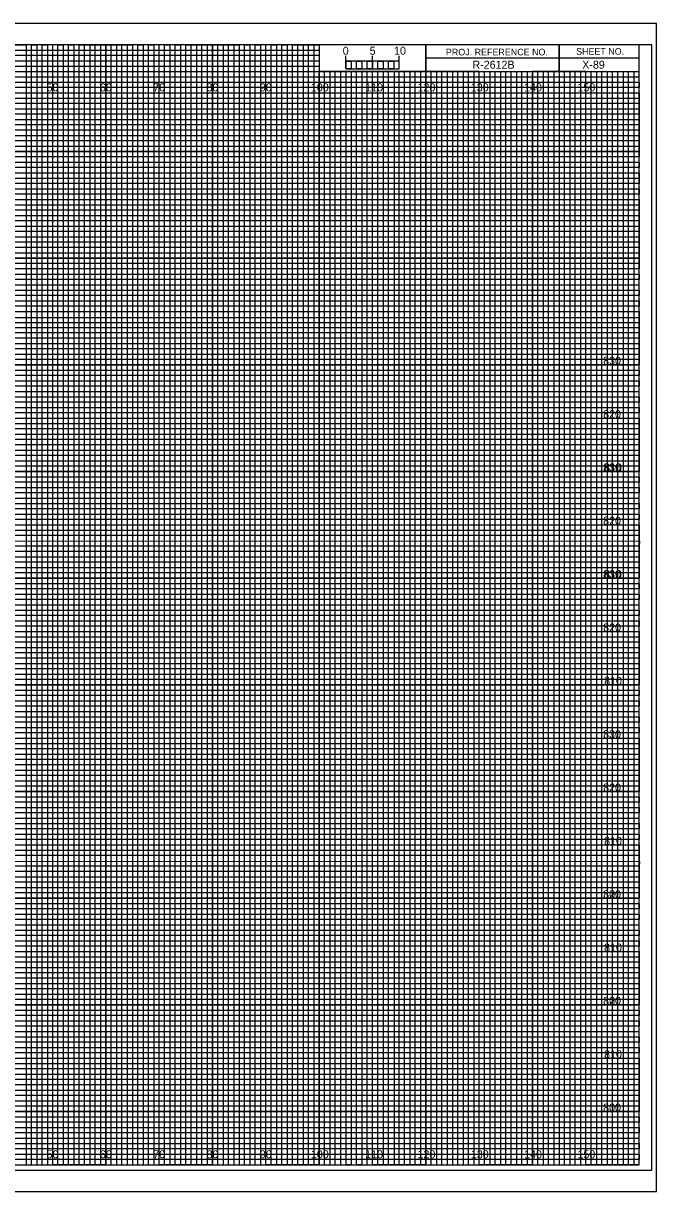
# Model space of a CAD drawing. Extents: x -13 to 323, y -5 to 214.
# Drawn here: x 204.5 to 323.3, y -5 to 214 of the extents above; entities that cross this region are included whole.
import ezdxf

# ---------------------------------------------------------------- set-up
doc = ezdxf.new("R2010")
doc.units = 0
for name, color, linetype in [('Prop XS Bar Scale Labels', 7, 'Continuous'), ('Prop XS Elevation Labels', 7, 'Continuous'), ('Prop XS Offset Labels', 7, 'Continuous'), ('Prop XS Project Number', 7, 'Continuous'), ('Prop XS Sheet Number', 7, 'Continuous'), ('Sheet Cross Section CELL', 7, 'Continuous'), ('Sheet Cross Section Grid Major CELL', 7, 'Continuous'), ('Sheet Cross Section Grid Middle CELL', 7, 'Continuous'), ('Sheet Cross Section Grid Minor 1 CELL', 7, 'Continuous'), ('Sheet Cross Section Grid Minor 2 CELL', 7, 'Continuous'), ('Sheet Cross Section Scale CELL', 7, 'Continuous'), ('Sheet Cutting Line CELL', 7, 'Continuous'), ('Sheet DOT Grid CELL', 7, 'Continuous'), ('Sheet Plot Border Inside CELL', 7, 'Continuous'), ('Sheet Plot Border Outside CELL', 7, 'Continuous')]:
    doc.layers.add(name, color=color, linetype=linetype)

msp = doc.modelspace()

# ---------------------------------------------------------------- linework, layer by layer
at = {"layer": 'Sheet Cross Section CELL'}
for p, q in [((305, 210), (305, 205)), ((305, 205), (305, 210)), ((280, 207.5), (280, 205)), ((320, 207.49), (280, 207.49)), ((280, 205), (320, 205))]:
    msp.add_line(p, q, dxfattribs=at)
for points in [[(320, 210), (0, 210), (0, 0), (320, 0)], [(280, 210), (260, 210), (260, 205.03), (280, 205.03)], [(320, 210), (280, 210), (280, 205), (320, 205)]]:
    msp.add_lwpolyline(points, close=True, dxfattribs=at)
at = {"layer": 'Sheet Cross Section Grid Major CELL'}
for p, q in [((210, 210), (200, 210)), ((210, 0), (210, 210)), ((230, 210), (220, 210)), ((220, 210), (220, 0)), ((230, 0), (230, 210)), ((250, 210), (240, 210)), ((240, 210), (240, 0)), ((250, 0), (250, 210)), ((260, 210), (260, 0)), ((270, 0), (270, 205)), ((290, 205), (280, 205)), ((280, 205), (280, 0)), ((290, 0), (290, 205)), ((310, 205), (300, 205)), ((300, 205), (300, 0)), ((310, 0), (310, 205)), ((220, 0), (210, 0)), ((240, 0), (230, 0)), ((260, 0), (250, 0)), ((280, 0), (270, 0)), ((300, 0), (290, 0)), ((320, 0), (310, 0)), ((320, 0), (320, 0))]:
    msp.add_line(p, q, dxfattribs=at)
for points in [[(0, 200), (320, 200), (320, 190), (0, 190)], [(0, 180), (320, 180), (320, 170), (0, 170)], [(0, 160), (320, 160), (320, 150), (0, 150)], [(0, 140), (320, 140), (320, 130), (0, 130)], [(0, 120), (320, 120), (320, 110), (0, 110)], [(0, 100), (320, 100), (320, 90), (0, 90)], [(0, 80), (320, 80), (320, 70), (0, 70)], [(0, 60), (320, 60), (320, 50), (0, 50)], [(0, 40), (320, 40), (320, 30), (0, 30)], [(0, 20), (320, 20), (320, 10), (0, 10)]]:
    msp.add_lwpolyline(points, dxfattribs=at)
at = {"layer": 'Sheet Cross Section Grid Middle CELL'}
for points in [[(195, 210), (205, 210), (205, 0), (215, 0), (215, 210), (225, 210), (225, 0), (235, 0), (235, 210), (245, 210), (245, 0), (255, 0), (255, 210), (259.93, 210), (260, 210), (260, 205), (264.99, 205), (264.99, 0), (275, 0), (275, 205), (285, 205), (285, 0), (295, 0), (295, 205), (305, 205), (305, 0), (315, 0), (315, 205)], [(0, 205), (275, 205)], [(0, 185), (320, 185), (320, 195), (0, 195)], [(0, 165), (320, 165), (320, 175), (0, 175)], [(0, 145), (320, 145), (320, 155), (0, 155)], [(0, 125), (320, 125), (320, 135), (0, 135)], [(0, 105), (320, 105), (320, 115), (0, 115)], [(0, 85), (320, 85), (320, 95), (0, 95)], [(0, 65), (320, 65), (320, 75), (0, 75)], [(0, 45), (320, 45), (320, 55), (0, 55)], [(0, 25), (320, 25), (320, 35), (0, 35)], [(0, 5), (320, 5), (320, 15), (0, 15)]]:
    msp.add_lwpolyline(points, dxfattribs=at)
at = {"layer": 'Sheet Cross Section Grid Minor 1 CELL'}
for p, q in [((0, 209), (260, 209)), ((260, 209), (260, 207.98)), ((260, 207.98), (0, 207.98)), ((0, 207), (260, 207)), ((260, 205.89), (0, 205.89)), ((260, 207), (260, 205.89)), ((0, 204), (320, 204))]:
    msp.add_line(p, q, dxfattribs=at)
for points in [[(0, 203), (270, 203), (320, 203), (320, 202), (0, 202)], [(0, 201), (320, 201), (320, 199), (0, 199)], [(0, 198), (320, 198), (320, 197), (0, 196.98)], [(0, 196), (320, 196), (320, 194), (0, 194)], [(0, 193), (320, 193), (320, 192), (0, 192)], [(0, 191), (320, 191), (320, 189), (0, 189)], [(0, 188), (320, 188), (320, 187), (0, 187)], [(0, 186), (320, 186), (320, 184), (0, 184)], [(0, 183), (320, 183), (320, 182), (0, 182)], [(0, 181), (320, 181), (320, 179), (0, 179)], [(0, 178), (320, 178), (320, 177), (0, 177)], [(0, 176), (320, 176), (320, 173.95), (320, 173), (320, 172), (0, 172)], [(0, 174), (320, 174), (320, 173), (0, 173)], [(0, 171), (320, 171), (320, 169), (0, 169.03)], [(0, 169.03), (320, 169), (320, 168), (0, 168)], [(0, 167), (320, 167), (320, 166), (0, 166)], [(0, 164), (320, 164), (320, 163), (0, 163)], [(0, 162), (320, 162), (320, 161), (0, 161)], [(-0.07, 158.89), (320, 158.89), (320, 157.88), (-0.07, 157.88)], [(0, 157), (320, 157), (320, 156), (0, 156)], [(0, 154), (320, 154), (320, 153), (0, 153)], [(0, 152), (320, 152), (320, 151), (0, 151)], [(0, 149), (320, 149), (320, 148), (0, 148)], [(0, 147), (320, 147), (320, 146), (0, 146)], [(0, 144), (320, 144), (320, 143), (0, 143)], [(0, 142), (320, 142), (320, 141), (0, 141)], [(0, 139), (320, 139), (319.99, 137.98), (0, 138)], [(0, 137), (320, 137), (320, 136), (0, 136)], [(0, 134), (320, 134), (320, 133), (0, 133)], [(0, 132), (320, 132), (320, 131), (0, 131)], [(0, 129), (320, 129), (320, 128), (0, 128)], [(0, 127), (320, 127), (320, 126), (0, 126)], [(0, 124), (320, 124), (320, 123), (0, 123)], [(0, 122), (320, 122), (320, 121), (0, 121)], [(0, 119), (320, 119), (320, 118), (0, 118)], [(0, 116.99), (320.07, 116.91), (320, 116), (0, 116)], [(0, 114), (320, 114), (320, 113), (0, 113)], [(0, 112), (320, 112), (320, 111), (0, 111)], [(0, 109), (320, 109), (320, 108), (0, 108)], [(0, 107), (320, 107), (320, 106), (0, 106)], [(0, 104), (320, 104), (320, 103), (0, 103)], [(0, 102), (320, 102), (320, 101), (0, 101)], [(0, 99), (320, 99), (320, 98), (0, 98)], [(0, 97), (320, 97), (320, 96), (0, 96)], [(0, 94), (320, 94), (320, 93), (0, 93)], [(0, 92), (320, 92), (320, 91), (0, 91)], [(0, 89), (320, 89), (320, 88), (0, 88)], [(0, 87), (320, 87), (320, 86), (0, 86)], [(0, 84), (320, 84), (320, 83), (0, 83)], [(0, 82), (320, 82), (320, 81), (0, 81)], [(0, 79), (320, 79), (319.99, 77.98), (0, 78)], [(0, 77), (320, 77), (320, 76), (0, 76)], [(0, 74), (320, 74), (320, 73), (0, 73)], [(0, 72), (320, 72), (320, 71), (0, 71)], [(0, 69), (320, 69), (320, 68), (0, 68)], [(0, 67), (320, 67), (320, 66), (0, 66)], [(0, 64), (320, 64), (320, 63), (0, 63)], [(0, 62), (320, 62), (320, 61), (0, 61)], [(0, 59), (320, 59), (320, 58), (0, 58)], [(0, 56.99), (320.07, 56.91), (320, 56), (0, 56)], [(0, 54), (320, 54), (320, 53), (0, 53)], [(0, 52), (320, 52), (320, 51), (0, 51)], [(0, 49), (320, 49), (320, 48), (0, 48)], [(0, 47), (320, 47), (320, 46), (0, 46)], [(0, 44), (320, 44), (320, 43), (0, 43)], [(0, 42), (320, 42), (320, 41), (0, 41)], [(0, 39), (320, 39), (320, 38), (0, 38)], [(0, 37), (320, 37), (320, 36), (0, 36)], [(0, 34), (320, 34), (320, 33), (0, 33)], [(0, 32), (320, 32), (320, 31), (0, 31)], [(0, 29), (320, 29), (320, 28), (0, 28)], [(0, 27), (320, 27), (320, 26), (0, 26)], [(0, 24), (320, 24), (320, 23), (0, 23)], [(0, 22), (320, 22), (320, 21), (0, 21)], [(0, 19), (320, 19), (320, 18), (0, 18)], [(0, 17), (320, 17), (320, 16), (0, 16)], [(0, 14), (320, 14), (320, 13), (0, 13)], [(0, 12), (320, 12), (320, 11), (0, 11)], [(0, 9), (320, 9), (320, 8), (0, 8)], [(0, 7), (320, 7), (320, 6), (0, 6)], [(0, 4), (320, 4), (320, 3), (0, 3)], [(0, 2), (320, 2), (320, 1), (0, 1)]]:
    msp.add_lwpolyline(points, dxfattribs=at)
at = {"layer": 'Sheet Cross Section Grid Minor 2 CELL'}
for p, q in [((267, 205), (266.01, 205)), ((266.01, 205), (266.01, 0)), ((267, 0), (267, 205)), ((269, 205), (268, 205)), ((268, 205), (268, 0)), ((269, 0), (269, 205)), ((266.01, 0), (265, 0)), ((268, 0), (267, 0))]:
    msp.add_line(p, q, dxfattribs=at)
for points in [[(205, 0), (206, 0), (206, 210), (207, 210), (207, 0)], [(207, 0), (208, 0), (208, 210), (209, 210), (209, 0)], [(210, 0), (211, 0), (211, 210), (212, 210), (212, 0)], [(212, 0), (213, 0), (213, 210), (214, 210), (214, 0)], [(215, 0), (216, 0), (216, 210), (217, 210), (217, 0)], [(217, 0), (218, 0), (218, 210), (219, 210), (219, 0)], [(220, 0), (221, 0), (221, 210), (222, 210), (222, 0)], [(222, 0), (223, 0), (223, 210), (224, 210), (224, 0)], [(225, 0), (226, 0), (226, 210), (227, 210), (227, 0)], [(227, 0), (228, 0), (228, 210), (229, 210), (229, 0)], [(230, 0), (231, 0), (231, 210), (232, 210), (232, 0)], [(232, 0), (233, 0), (233, 210), (234, 210), (234, 0)], [(235, 0), (236, 0), (236, 210), (237, 210), (237, 0)], [(237, 0), (238, 0), (238, 210), (239, 210), (239, 0)], [(240, 0), (241, 0), (241, 210), (242, 210), (242, 0)], [(242, 0), (243, 0), (243, 210), (244, 210), (244, 0)], [(245, 0), (246, 0), (246, 210), (247, 210), (247, 0)], [(247, 0), (248, 0), (248, 210), (249, 210), (249, 0)], [(250, 0), (251, 0), (251, 210), (252, 210), (252, 0)], [(252, 0), (253, 0), (253, 210), (254, 210), (254, 0)], [(255, 0), (256, 0), (256, 210), (257, 210), (257, 0)], [(257, 0), (258, 0), (258, 210), (259, 210), (259, 0)], [(260, 0), (261, 0), (261, 205), (262.02, 205), (262.02, 0)], [(262, 0), (263, 0), (263, 205), (263.99, 205), (263.99, 0)], [(270, 0), (270.98, 0), (270.98, 205), (272, 205), (272, 0)], [(272, 0), (273, 0), (273, 205), (274.05, 205), (274.05, 0)], [(275, 0), (276, 0), (276, 205), (277, 205), (277, 0)], [(277, 0), (278, 0), (278, 205), (279, 205), (279, 0)], [(280, 0), (281, 0), (281, 205), (282, 205), (282, 0)], [(282, 0), (283, 0), (283, 205), (284, 205), (284, 0)], [(285, 0), (286, 0), (286, 205), (287, 205), (287, 0)], [(287, 0), (288, 0), (288, 205), (289, 205), (289, 0)], [(290, 0), (291, 0), (291, 205), (292, 205), (292, 0)], [(292, 0), (293, 0), (293, 205), (294, 205), (294, 0)], [(295, 0), (296, 0), (296, 205), (297, 205), (297, 0)], [(297, 0), (298, 0), (298, 205), (299, 205), (299, 0)], [(300, 0), (301, 0), (301, 205), (302, 205), (302, 0)], [(302, 0), (303, 0), (303, 205), (304, 205), (304, 0)], [(305, 0), (306, 0), (306, 205), (307, 205), (307, 0)], [(307, 0), (308, 0), (308, 205), (309, 205), (309, 0)], [(310, 0), (311, 0), (311, 205), (312, 205), (312, 0)], [(312, 0), (313, 0), (313, 205), (314, 205), (314, 0)], [(315, 0), (316, 0), (316, 205), (317, 205), (317, 0)], [(317, 0), (318, 0), (318, 205), (319, 205), (319, 0)]]:
    msp.add_lwpolyline(points, dxfattribs=at)
at = {"layer": 'Sheet Cross Section Scale CELL'}
for p, q in [((265, 205.49), (265, 207.9)), ((265, 206.9), (265, 207.9)), ((270, 205.49), (270, 207.9)), ((275, 205.49), (275, 207.9)), ((275, 206.9), (275, 207.9))]:
    msp.add_line(p, q, dxfattribs=at)
for points in [[(275, 206.9), (265, 206.9), (265, 205.49), (275, 205.49)], [(265, 206.9), (266, 206.9), (266, 205.49), (265, 205.49)], [(267, 206.9), (268, 206.9), (268, 205.49), (267, 205.49)], [(269, 206.9), (270, 206.9), (270, 205.49), (269, 205.49)], [(271, 206.9), (272, 206.9), (272, 205.49), (271, 205.49)], [(273, 206.9), (274, 206.9), (274, 205.49), (273, 205.49)]]:
    msp.add_lwpolyline(points, close=True, dxfattribs=at)
at = {"layer": 'Sheet Cutting Line CELL'}
for p, q in [((323.3, 214), (-13.4, 214)), ((-13.4, -5), (323.3, -5))]:
    msp.add_line(p, q, dxfattribs=at)
at = {"layer": 'Sheet DOT Grid CELL'}
for p, q in [((210, 0), (210, 210)), ((220, 0), (220, 210)), ((230, 0), (230, 210)), ((240, 0), (240, 210)), ((250, 0), (250, 210)), ((260, 0), (260, 204.69)), ((270, 0), (270, 204.69)), ((280, 0), (280, 204.69)), ((290, 0), (290, 204.69)), ((300, 0), (300, 204.69)), ((310, 0), (310, 204.69)), ((0, 200), (320, 200)), ((0, 190), (320, 190)), ((0, 180), (320, 180)), ((0, 170), (320, 170)), ((0, 160), (320, 160)), ((0, 150), (320, 150)), ((0, 140), (320, 140)), ((0, 130), (320, 130)), ((0, 120), (320, 120)), ((0, 110), (320, 110)), ((0, 100), (320, 100)), ((0, 90), (320, 90)), ((0, 80), (320, 80)), ((0, 70), (320, 70)), ((0, 60), (320, 60)), ((0, 50), (320, 50)), ((0, 40), (320, 40)), ((0, 30), (320, 30)), ((0, 20), (320, 20)), ((0, 10), (320, 10))]:
    msp.add_line(p, q, dxfattribs=at)
at = {"layer": 'Sheet Plot Border Inside CELL'}
msp.add_lwpolyline([(-10.8, -1), (322.4, -1), (322.4, 210), (-10.8, 210)], close=True, dxfattribs=at)
at = {"layer": 'Sheet Plot Border Outside CELL'}
msp.add_lwpolyline([(-13.4, -5), (323.3, -5), (323.3, 214), (-13.4, 214)], close=True, dxfattribs=at)

# ---------------------------------------------------------------- texts
at = {"layer": 'Prop XS Bar Scale Labels'}
for s, p in [('5', (269.47, 208.12)), ('10', (274.04, 208.12))]:
    msp.add_text(s, height=1.5, dxfattribs=at).set_placement(p)
at = {"layer": 'Prop XS Elevation Labels'}
for s, p in [('830', (313.26, 150)), ('820', (313.26, 140)), ('830', (313.26, 130)), ('810', (313.44, 130)), ('820', (313.26, 120)), ('830', (313.26, 110)), ('810', (313.44, 110)), ('820', (313.26, 100)), ('810', (313.44, 90)), ('830', (313.26, 80)), ('820', (313.26, 70)), ('810', (313.44, 60)), ('820', (313.26, 50)), ('800', (313.26, 50)), ('810', (313.44, 40)), ('820', (313.26, 30)), ('800', (313.26, 30)), ('810', (313.44, 20)), ('800', (313.26, 10))]:
    msp.add_text(s, height=1.5, dxfattribs=at).set_placement(p)
at = {"layer": 'Prop XS Offset Labels'}
for s, p in [('50', (208.86, 201.25)), ('60', (218.86, 201.25)), ('70', (228.86, 201.25)), ('80', (238.86, 201.25)), ('90', (248.86, 201.25)), ('100', (258.44, 201.25)), ('110', (268.62, 201.25)), ('120', (278.44, 201.25)), ('130', (288.44, 201.25)), ('140', (298.44, 201.25)), ('150', (308.44, 201.25)), ('50', (208.86, 1.25)), ('60', (218.86, 1.25)), ('70', (228.86, 1.25)), ('80', (238.86, 1.25)), ('90', (248.86, 1.25)), ('100', (258.44, 1.25)), ('110', (268.62, 1.25)), ('120', (278.44, 1.25)), ('130', (288.44, 1.25)), ('140', (298.44, 1.25)), ('150', (308.44, 1.25))]:
    msp.add_text(s, height=1.5, dxfattribs=at).set_placement(p)
at = {"layer": 'Prop XS Project Number'}
msp.add_text('R-2612B', height=1.5, dxfattribs=at).set_placement((288.74, 205.5))
at = {"layer": 'Prop XS Sheet Number'}
msp.add_text('X-89', height=1.5, dxfattribs=at).set_placement((309.33, 205.5))
at = {"layer": 'Sheet Cross Section CELL'}
for s, p in [('PROJ. REFERENCE NO.', (283.77, 207.99)), ('SHEET NO.', (308.19, 208.12))]:
    msp.add_text(s, height=1.25, dxfattribs=at).set_placement(p)
at = {"layer": 'Sheet Cross Section Scale CELL'}
msp.add_text('0', height=1.5, dxfattribs=at).set_placement((264.41, 208.12))

doc.saveas('drawing.dxf')
